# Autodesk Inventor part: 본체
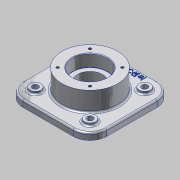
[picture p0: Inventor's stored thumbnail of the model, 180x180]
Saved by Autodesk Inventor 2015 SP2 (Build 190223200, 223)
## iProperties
Created: 2015-07
Part Number: 본체
Material: 알루미늄 6061
Document SubType Name: Modeling
Designer: AMC
Density: 2.7 g/cm^3
Appearance: 알루미늄 - 평지
Mass: 1459.27 g
Surface Area: 800.934 cm^2
Volume: 540.471 cm^3
Author: AMC
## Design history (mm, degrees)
sketch "스케치1"
  geometry: L1 (-75, -75)-(75, -75); L2 (75, -75)-(75, 75); L3 (75, 75)-(-75, 75); L4 (-75, 75)-(-75, -75); L5 (-75, -75)-(75, 75); L6 (75, -75)-(-75, 75); 1 further point
  constraints: 12 end point, 2 midpoint, 2 parallel, 1 horizontal, 1 perpendicular
  dimensions: "d0" = 150 distance of L3.end L2.end; "d1" = 150 distance of L2.end L1.end
extrude "돌출1" new body sketch "스케치1" distance "d2" = 12; taper "d3" = 0 deg
sketch "스케치2"
  geometry: C1 r 50 at (0, 0); 1 further point
  constraints: 1 centre point, 1 coincident
  dimensions: "d4" = 100 diameter of C1
extrude "돌출2" join sketch "스케치2" distance "d5" = 23; taper "d7" = 0 deg; dims "d6" = 47, "d8" = 0
fillet "모깎기1" dims "d9" = 30
sketch "스케치3"
  geometry: L1 (49, -49)-(-49, -49); L2 (-49, -49)-(-49, 49); L3 (-49, 49)-(49, 49); L4 (49, 49)-(49, -49); L5 (49, -49)-(-49, 49); L6 (-49, -49)-(49, 49); C1 r 10 at (-49, 49); 1 further point
  constraints: 12 end point, 2 midpoint, 2 parallel, 1 centre point, 1 coincident, 1 horizontal, 1 perpendicular
  dimensions: "d10" = 98 distance of L2.end L3.end; "d11" = 98 distance of L1.end L2.end; "d12" = 20 diameter of C1
extrude "돌출3" join sketch "스케치3" distance "d13" = 5; taper "d14" = 0 deg
hole "구멍1" diameter "d17" = 11; stored, may be unused: countersink angle "d21" = 90 deg, drill point angle "d23" = 118 deg; dims "d15" = 10, "d16" = 10, "d18" = 6, "d19" = 4, "d20" = 2, "d22" = 8
hole "구멍2" diameter "d29" = 62; stored, may be unused: countersink angle "d33" = 90 deg, drill point angle "d35" = 0 deg; dims "d27" = 10, "d28" = 10, "d30" = 6, "d31" = 4, "d32" = 2, "d34" = 22
hole "구멍3" diameter "d38" = 62; stored, may be unused: countersink angle "d42" = 90 deg, drill point angle "d44" = 0 deg; dims "d36" = 10, "d37" = 10, "d39" = 6, "d40" = 4, "d41" = 2, "d43" = 22
hole "구멍4" diameter "d47" = 45; stored, may be unused: countersink angle "d51" = 90 deg, drill point angle "d53" = 0 deg; dims "d45" = 10, "d46" = 10, "d48" = 6, "d49" = 4, "d50" = 2, "d52" = 22
sketch "스케치4"
  geometry: L1 (0, 0)-(-41, 0); L2 (0, 0)-(-28.991, 28.991); A1 r 41 centre (0, 0) between (-41, 0) and (-28.991, 28.991); 1 further point
  constraints: 4 end point, 2 point on circle, 1 centre point, 1 coincident, 1 horizontal
  dimensions: "d54" = 82 diameter of A1; "d55" = 45 deg angle of L2 L1
hole "구멍5" sketch "스케치4" at (-28.991, 28.991) diameter "d56" = 4.917; stored, may be unused: countersink angle "d60" = 90 deg, drill point angle "d62" = 118 deg; dims "d57" = 10, "d58" = 4, "d59" = 2, "d61" = 13
sketch "스케치5"
  geometry: L1 (0, 0)-(-41, 0); L2 (0, 0)-(-28.991, 28.991); A1 r 41 centre (0, 0) between (-41, 0) and (-28.991, 28.991); 1 further point
  constraints: 4 end point, 2 point on circle, 1 centre point, 1 coincident, 1 horizontal
  dimensions: "d63" = 82 diameter of A1; "d64" = 45 deg angle of L2 L1
hole "구멍6" sketch "스케치5" at (-28.991, 28.991) diameter "d65" = 4.917; stored, may be unused: countersink angle "d69" = 90 deg, drill point angle "d71" = 118 deg; dims "d66" = 10, "d67" = 4, "d68" = 2, "d70" = 13
fillet "모깎기2" dims "d78" = 3
fillet "모깎기3" dims "d79" = 0.3
chamfer "모따기1" distance "d80" = 1; stored, may be unused: second distance "d81" = 2, angle "d82" = 45 deg
sketch "스케치6"
  geometry: 2 further points
  constraints: 1 vertical alignment, 1 other
  dimensions: "d83" = 65 distance of point (0, 0) point (0, 65)
feature "엠보싱1" sketch "스케치6" dims "d10" = 98, "d11" = 98, "d12" = 20, "d84" = 1, "d85" = 0
node "솔리드1"
pattern_circular "원형 패턴1" dims angle "d25" = 360 deg
pattern_circular "원형 패턴2" dims angle "d73" = 360 deg
pattern_circular "원형 패턴3" dims angle "d76" = 360 deg
